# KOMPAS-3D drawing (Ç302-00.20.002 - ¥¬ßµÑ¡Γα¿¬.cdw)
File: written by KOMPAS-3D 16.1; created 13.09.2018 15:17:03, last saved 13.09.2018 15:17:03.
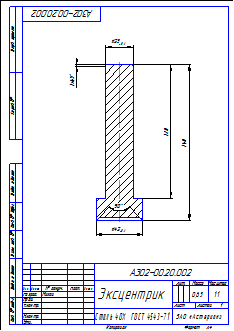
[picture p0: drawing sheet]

Sheet 1: A4, portrait

Title block, sheet 1: name: Эксцентрик; designation: А302-00.20.002; material: Сталь 40Х  ГОСТ 4543-71; mass: 0,65; scale: 1:1; sheets: 1; organisation: ЗАО «Астерион»; sheet format: A4; drawn by: Милов

Views: Вид 1, Местный разрез 1, Спереди, Проекционный вид 2, Вид:3
Referenced files in Z:\Мембранные насосы\Мембранный электропривод\А302-00.00.000 - ASTRA-302 (МЭ200)\3Д\Доработка\: Шаблон А302-00.20.002 - Эксцентрик.m3d
Dimensions and other numbers on the sheet: 25; 120; 140; 42; 1; 1:1; 0,65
